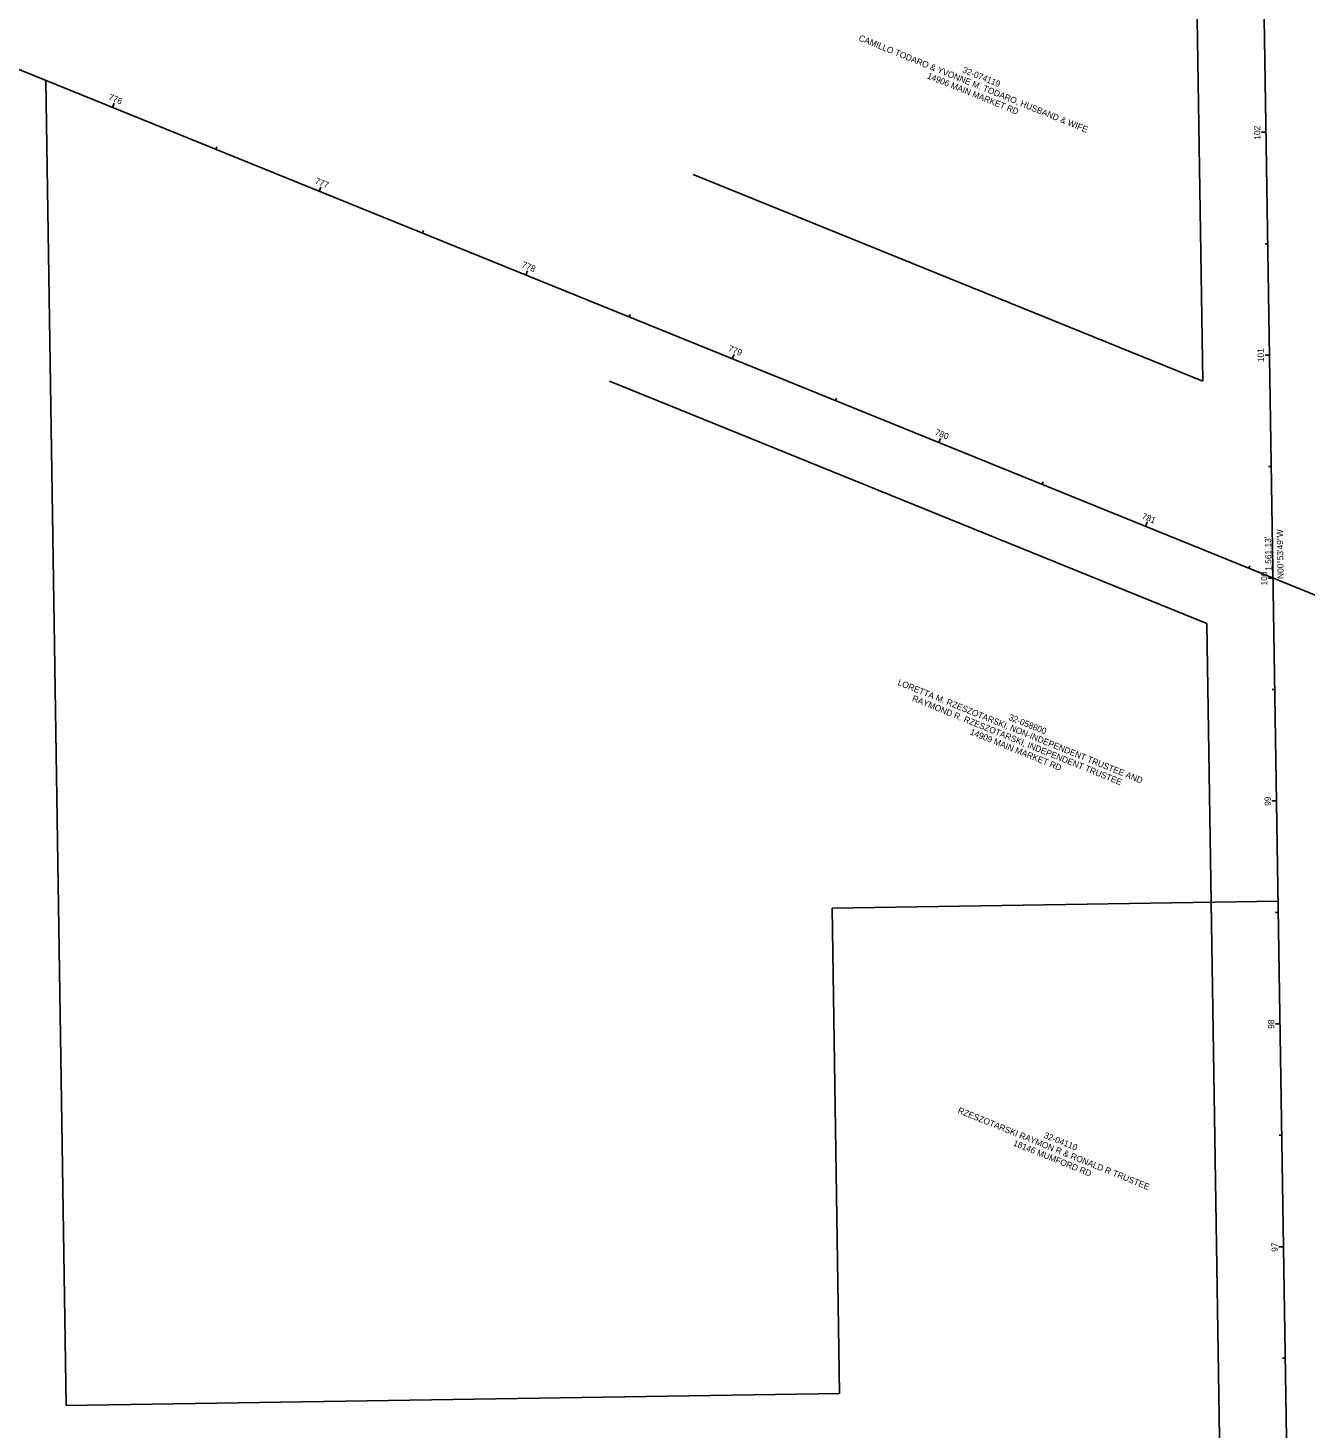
# Model space of a CAD drawing. Extents: x 2345526 to 2352728, y 625359 to 628213.
# Drawn here: x 2350102 to 2350675, y 625748 to 626376 of the extents above; entities that cross this region are included whole.
import ezdxf

# ---------------------------------------------------------------- set-up
doc = ezdxf.new("R2010")
doc.units = 0
for name, color, linetype in [('_CIVIL_CONSTRUCTION', 7, 'Continuous'), ('DR_P_Cells', 7, 'Continuous'), ('DR_P_Ditch', 7, 'Continuous'), ('DR_P_Erosion_Control', 7, 'Continuous'), ('DR_P_Headwall', 7, 'Continuous'), ('DR_X_GenericNode', 7, 'Continuous'), ('DR_X_Storm_Sewer', 7, 'Continuous'), ('GK_Drainage_Nodes', 7, 'Continuous'), ('RW_X_CL_1000_Distances', 7, 'Continuous'), ('RW_X_CL_500_Distances', 7, 'Continuous'), ('RW_X_Text', 7, 'Continuous'), ('SC_ProfileRun1', 7, 'Continuous'), ('SC_Scratch1', 7, 'Continuous')]:
    doc.layers.add(name, color=color, linetype=linetype)

msp = doc.modelspace()

# ---------------------------------------------------------------- linework, layer by layer
at = {"layer": 'DR_P_Ditch'}
for p, q in [((2350672.35, 625359.95), (2350647.92, 626920.89)), ((2348868.68, 626855.7), (2350975.06, 626001.36))]:
    msp.add_line(p, q, dxfattribs=at)
at = {"layer": 'DR_P_Headwall'}
for p, q in [((2350510.49, 626189.79), (2350511.24, 626191.64)), ((2350660.31, 626129.02), (2350658.31, 626128.99))]:
    msp.add_line(p, q, dxfattribs=at)
at = {"layer": 'DR_X_GenericNode'}
for p, q in [((2350617.92, 626920.42), (2350628.93, 626217.29)), ((2350400.28, 626310.03), (2350628.93, 626217.29)), ((2350362.69, 626217.36), (2350630.63, 626108.69)), ((2350630.63, 626108.69), (2350642.36, 625359.48))]:
    msp.add_line(p, q, dxfattribs=at)
at = {"layer": 'DR_X_Storm_Sewer'}
for p, q in [((2350109.87, 626352.28), (2350118.98, 625757.88)), ((2350462.56, 625980.97), (2350662.58, 625984.04)), ((2350465.9, 625763.2), (2350462.56, 625980.97)), ((2350118.98, 625757.88), (2350465.9, 625763.2))]:
    msp.add_line(p, q, dxfattribs=at)
at = {"layer": 'GK_Drainage_Nodes'}
for p, q in [((2350139.82, 626340.13), (2350140.27, 626341.24)), ((2350657.18, 626329), (2350655.98, 626328.98)), ((2350232.49, 626302.55), (2350232.94, 626303.66)), ((2350325.15, 626264.96), (2350325.6, 626266.07)), ((2350417.82, 626227.38), (2350418.27, 626228.49)), ((2350658.75, 626229.01), (2350657.55, 626228.99)), ((2350510.49, 626189.79), (2350511.24, 626191.64)), ((2350603.16, 626152.2), (2350603.61, 626153.32)), ((2350660.31, 626129.02), (2350658.31, 626128.99)), ((2350661.88, 626029.03), (2350660.68, 626029.02)), ((2350663.44, 625929.05), (2350662.24, 625929.03)), ((2350665.01, 625829.06), (2350663.81, 625829.04))]:
    msp.add_line(p, q, dxfattribs=at)
at = {"layer": 'SC_Scratch1'}
for p, q in [((2350139.82, 626340.13), (2350140.57, 626341.99)), ((2350657.18, 626329), (2350655.18, 626328.97)), ((2350186.15, 626321.34), (2350186.6, 626322.45)), ((2350232.49, 626302.55), (2350233.24, 626304.4)), ((2350278.82, 626283.75), (2350279.27, 626284.87)), ((2350657.96, 626279), (2350656.77, 626278.98)), ((2350325.15, 626264.96), (2350325.9, 626266.81)), ((2350371.49, 626246.17), (2350371.94, 626247.28)), ((2350417.82, 626227.38), (2350418.57, 626229.23)), ((2350658.75, 626229.01), (2350656.75, 626228.98)), ((2350464.15, 626208.58), (2350464.61, 626209.69)), ((2350510.49, 626189.79), (2350511.24, 626191.64)), ((2350659.53, 626179.02), (2350658.33, 626179)), ((2350556.82, 626171), (2350557.27, 626172.11)), ((2350603.16, 626152.2), (2350603.91, 626154.06)), ((2350649.49, 626133.41), (2350649.94, 626134.52)), ((2350660.31, 626129.02), (2350658.31, 626128.99)), ((2350661.1, 626079.03), (2350659.9, 626079.01)), ((2350661.88, 626029.03), (2350659.88, 626029)), ((2350662.66, 625979.04), (2350661.46, 625979.02)), ((2350663.44, 625929.05), (2350661.44, 625929.01)), ((2350664.23, 625879.05), (2350663.03, 625879.03)), ((2350665.01, 625829.06), (2350663.01, 625829.03)), ((2350665.79, 625779.06), (2350664.59, 625779.05))]:
    msp.add_line(p, q, dxfattribs=at)

# ---------------------------------------------------------------- texts
at = {"layer": '_CIVIL_CONSTRUCTION'}
msp.add_text('N00°53\'49"W', height=2.8, rotation=90.89691, dxfattribs=at).set_placement((2350665.12, 626128.63))
at = {"layer": 'DR_P_Cells'}
msp.add_text('N00°53\'49"W', height=2.8, rotation=90.89691, dxfattribs=at).set_placement((2350665.12, 626128.63))
at = {"layer": 'DR_P_Erosion_Control'}
msp.add_text("1,561.13'", height=2.8, rotation=90.89691, dxfattribs=at).set_placement((2350659.7, 626132.3))
at = {"layer": 'DR_P_Headwall'}
for s, rotation, p in [('780', 337.92278, (2350508.41, 626193.38)), ('100', 90.89691, (2350657.82, 626125.7))]:
    msp.add_text(s, height=2.8, rotation=rotation, dxfattribs=at).set_placement(p)
at = {"layer": 'GK_Drainage_Nodes'}
for s, rotation, p in [('780', 337.92278, (2350508.41, 626193.38)), ('100', 90.89691, (2350657.82, 626125.7))]:
    msp.add_text(s, height=2.8, rotation=rotation, dxfattribs=at).set_placement(p)
at = {"layer": 'RW_X_CL_1000_Distances'}
msp.add_text("1,561.13'", height=2.8, rotation=90.89691, dxfattribs=at).set_placement((2350659.7, 626132.3))
at = {"layer": 'RW_X_CL_500_Distances'}
msp.add_text("1,561.13'", height=2.8, rotation=90.89691, dxfattribs=at).set_placement((2350659.7, 626132.3))
at = {"layer": 'RW_X_Text'}
for s, p in [('CAMILLO TODARO & YVONNE M. TODARO, HUSBAND & WIFE', (2350474.21, 626370.24)), ('32-074119', (2350520.77, 626355.89)), ('14906 MAIN MARKET RD', (2350504.9, 626353.26)), ('LORETTA M. RZESZOTARSKI, NON-INDEPENDENT TRUSTEE AND', (2350491.74, 626081.13)), ('RAYMOND R. RZESZOTARSKI, INDEPENDENT TRUSTEE', (2350498.19, 626073.98)), ('32-058800', (2350541.43, 626065.51)), ('14909 MAIN MARKET RD', (2350524.14, 626058.93)), ('RZESZOTARSKI RAYMON R & RONALD R TRUSTEE', (2350518.68, 625889.12)), ('32-04110', (2350557.25, 625878.01)), ('18146 MUMFORD RD', (2350543.53, 625874.51))]:
    msp.add_text(s, height=2.8, rotation=337.92278, dxfattribs=at).set_placement(p)
at = {"layer": 'SC_ProfileRun1'}
msp.add_text('N00°53\'49"W', height=2.8, rotation=90.89691, dxfattribs=at).set_placement((2350665.12, 626128.63))
at = {"layer": 'SC_Scratch1'}
for s, rotation, p in [('776', 337.92278, (2350137.73, 626343.73)), ('102', 90.89691, (2350654.69, 626325.68)), ('777', 337.92278, (2350230.33, 626306.12)), ('778', 337.92278, (2350323.07, 626268.55)), ('779', 337.92278, (2350415.76, 626230.96)), ('101', 90.89691, (2350656.25, 626225.86)), ('780', 337.92278, (2350508.41, 626193.38)), ('781', 337.92278, (2350601.23, 626155.73)), ('100', 90.89691, (2350657.82, 626125.7)), ('99', 90.89691, (2350659.37, 626026.83)), ('98', 90.89691, (2350660.93, 625926.82)), ('97', 90.89691, (2350662.5, 625826.77))]:
    msp.add_text(s, height=2.8, rotation=rotation, dxfattribs=at).set_placement(p)

doc.saveas('drawing.dxf')
